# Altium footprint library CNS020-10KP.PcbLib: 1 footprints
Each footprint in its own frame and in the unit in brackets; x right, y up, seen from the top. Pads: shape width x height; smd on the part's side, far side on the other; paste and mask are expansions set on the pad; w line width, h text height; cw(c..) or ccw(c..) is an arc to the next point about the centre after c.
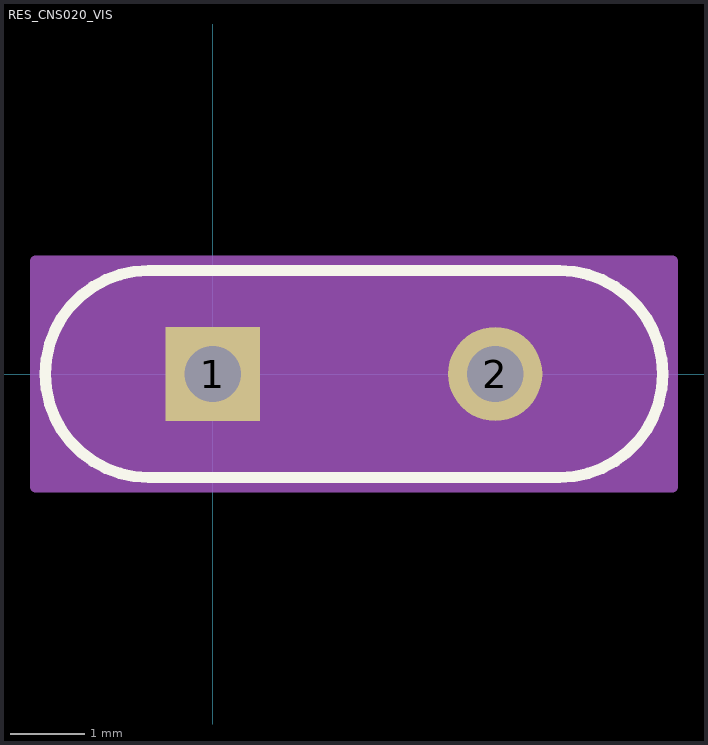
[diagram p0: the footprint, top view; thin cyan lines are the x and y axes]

## RES_CNS020_VIS [mil]
pads (2):
  rect 50x50 hole 30 paste-25 mask+0: 1(0,0)
  round 50 hole 30 paste-25 mask+0: 2(150,0)
Top Overlay:
  lines w6: -34,-55 184,-55 ccw(c184,0) 239,0 ccw(c184,0) 184,55 -34,55 ccw(c-34,0) -34,-55
  text ".Designator" at -62.5,-25 h50
Mechanical 13:
  lines w1: -34,-50 184,-50 ccw(c184,0) 184,50 -34,50 ccw(c-34,0) -34,-50
  text ".Designator" at -62.5,-25 h50
Mechanical 15:
  region: 244,-60 -94,-60 -94,60 244,60
  lines w6: -94,-60 -94,60 244,60 244,-60 -94,-60
3D body "RES_CNS020_VIS.step": height 260, standoff -156.81, extent -84.02,-50 234.02,50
